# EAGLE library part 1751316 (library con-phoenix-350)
MKDS 1/ 9-3,5 Printklemme Nennstrom: 10 A Bemessungsspannung: 160 V Raster: 3,5 mm Polzahl: 9 Montageart: Löten Anschlussart: Schraubanschluss Anschlussrichtung vom Leiter zur Platine: 0° Source: http://eshop.phoenixcontact.com .. 1751316.pdf
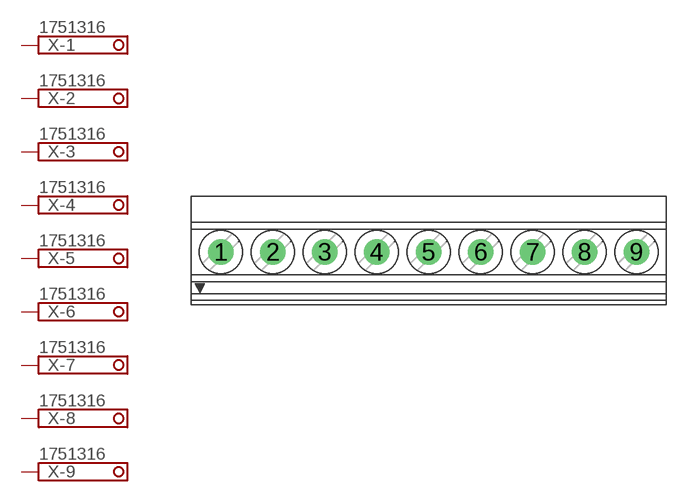
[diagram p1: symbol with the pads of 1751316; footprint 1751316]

Designator prefix X; gates -1=SCHRAUBKLEMME -2=SCHRAUBKLEMME -3=SCHRAUBKLEMME -4=SCHRAUBKLEMME -5=SCHRAUBKLEMME -6=SCHRAUBKLEMME -7=SCHRAUBKLEMME -8=SCHRAUBKLEMME -9=SCHRAUBKLEMME

## 1751316 (OC_FARNELL: unknown; OC_NEWARK: unknown)  [1751316]
1  -1:K  pas
2  -2:K  pas
3  -3:K  pas
4  -4:K  pas
5  -5:K  pas
6  -6:K  pas
7  -7:K  pas
8  -8:K  pas
9  -9:K  pas

## Footprint 1751316 (pad centres in mm)
MKDS 1/ 9-3,5 Printklemme Nennstrom: 10 A Bemessungsspannung: 160 V Raster: 3,5 mm Polzahl: 9 Montageart: Löten Anschlussart: Schraubanschluss Anschlussrichtung vom Leiter zur Platine: 0° Source: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
drill 1.1 pad 1.7 round: 1 -13.973,-0.1; 2 -10.473,-0.1; 3 -6.973,-0.1; 4 -3.473,-0.1; 5 0.028,-0.1; 6 3.527,-0.1; 7 7.027,-0.1; 8 10.527,-0.1; 9 14.027,-0.1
